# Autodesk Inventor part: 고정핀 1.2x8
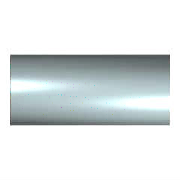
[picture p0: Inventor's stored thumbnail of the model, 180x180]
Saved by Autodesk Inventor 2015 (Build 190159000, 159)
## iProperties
IsCustomPart: 1
Created: 2012-02
Part Number: 고정핀 1.2x8
Material: 강철, 연강
Description: 평행 핀
Document SubType Name: Modeling
Standard: KS B 1320
Designer: P15F
Standards Organization: KS
Language: ko-KR
Size Designation: C 1.2 x  8
Categories: <MemberInstance><Categories><Category DisplayName="조임쇠" InternalName="e4da775c-781d-43d5-af7c-5136215cf5a6" Mnemonic="FSTN"><Category DisplayName="핀" InternalNa
Density: 1 g/cm^3
Appearance: 노란색
Author: P15F
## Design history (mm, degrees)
sketch "스케치1"
  geometry: C1 r 0.6 at (0, 0); 1 further point
  constraints: 1 centre point, 1 coincident
  dimensions: "d1" = 1.2 diameter of C1 (= NND)
extrude "본체" new body sketch "스케치1" distance "d2" = 8 (= NLG); taper "d3" = 0 deg
node "작업 평면1"
body "Solid1"
other parameters: "NND" = 1.2 [user parameter; used in 1 equation term], "NLG" = 8 [user parameter; used in 1 equation term], "d8" = 0, "d9" = 0, "d10" = 0
